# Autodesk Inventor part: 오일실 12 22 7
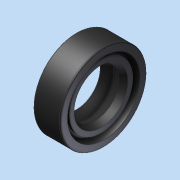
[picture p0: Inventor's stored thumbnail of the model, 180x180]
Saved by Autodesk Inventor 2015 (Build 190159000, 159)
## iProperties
Created: 2024-06
Part Number: 오일실 12 22 7
Material: 일반
Document SubType Name: Modeling
Designer: Administrator
Density: 1 g/cm^3
Appearance: 기본값
Author: Administrator
Author: jhkim
Description: 오일-실
Creation Date: 2024-05-29
Sending System: Autodesk Inventor 2025
Preprocessor: ST-DEVELOPER v20
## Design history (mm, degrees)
node "오일실 12 22 71"
body "Solid1"
node "기준1"
